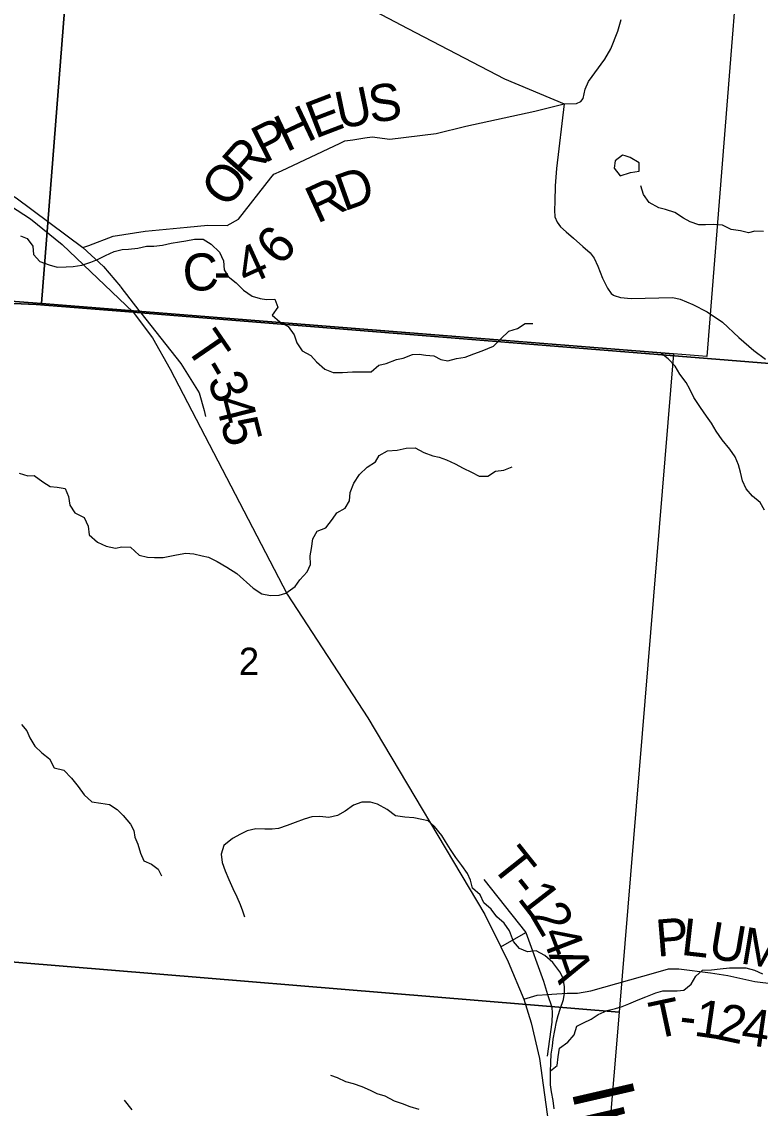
# Model space of a CAD drawing. Extents: x 1715311 to 2083412, y 146837 to 553079.
# Drawn here: x 1973537 to 1979519, y 339371 to 348173 of the extents above; entities that cross this region are included whole.
import ezdxf

# ---------------------------------------------------------------- set-up
doc = ezdxf.new("R2010")
doc.units = 0
for name, color, linetype in [('GM_X_County_Road', 7, 'Continuous'), ('GM_X_County_Road_Text', 7, 'Continuous'), ('GM_X_Minor_Lake', 7, 'Continuous'), ('GM_X_Minor_River', 7, 'Continuous'), ('GM_X_Minor_River_Text', 7, 'Continuous'), ('GM_X_Section', 7, 'Continuous'), ('GM_X_Section_Text', 7, 'Continuous'), ('GM_X_Township', 7, 'Continuous'), ('GM_X_Township_Road', 7, 'Continuous'), ('GM_X_Township_Road_Text', 7, 'Continuous'), ('GM_X_Township_ROW', 7, 'Continuous'), ('GM_X_US_Route', 7, 'Continuous')]:
    doc.layers.add(name, color=color, linetype=linetype)

msp = doc.modelspace()

# ---------------------------------------------------------------- linework, layer by layer
at = {"layer": 'GM_X_County_Road'}
for points in [[(1976315.6, 347231.9), (1976375.3, 347240.8), (1976518, 347221.4), (1976893.4, 347268.9), (1977134.7, 347326.6), (1977693.6, 347448.3), (1977931.9, 347509.1), (1978031.9, 347510.2), (1978065.9, 347526.7), (1978085.5, 347551.4), (1978102, 347625.6), (1978126.8, 347689.6), (1978260.8, 347869.1), (1978310.3, 347953.6), (1978366, 348098), (1978392.8, 348190.8)], [(1974080.1, 346361.4), (1974277.8, 346435.5), (1974537.4, 346476.2), (1974707.9, 346491.5), (1974878.3, 346509.3), (1975043.7, 346524.6), (1975201.5, 346522), (1975293.1, 346572.9), (1975554.3, 346908.1), (1975579.5, 346937.2), (1975640.1, 346965.7), (1976117.7, 347190.6), (1976154.1, 347207.7), (1976218.7, 347217.4), (1976315.6, 347231.9)], [(1972738.2, 347039.8), (1972777.2, 347075.4), (1972816.1, 347111), (1972838.6, 347131.6), (1972902.1, 347091.5), (1973491.6, 346746), (1974033.6, 346343.9), (1974080.1, 346361.4)]]:
    msp.add_lwpolyline(points, dxfattribs=at)
at = {"layer": 'GM_X_Minor_Lake'}
for points in [[(1978424.9, 347085.7), (1978402.6, 347092.6), (1978344.8, 347046.4), (1978336.9, 346986.3), (1978385, 346924.3)], [(1978385, 346924.3), (1978468.8, 346952.6), (1978538.7, 346962.7), (1978538.5, 347028.8), (1978466.6, 347072.7), (1978424.9, 347085.7)]]:
    msp.add_lwpolyline(points, dxfattribs=at)
at = {"layer": 'GM_X_Minor_River'}
for points in [[(1979544.2, 346474.2), (1979476.2, 346476), (1979424.3, 346461.9), (1979358.4, 346479.8), (1979284.5, 346489.6), (1979212.5, 346525.5), (1979138.6, 346531.4), (1979074.7, 346527.2), (1979020.8, 346529.1), (1978950.8, 346553), (1978896.9, 346581), (1978826.9, 346626.9), (1978750.9, 346650.7), (1978697, 346664.6), (1978619, 346708.5), (1978573, 346774.5), (1978550.9, 346842.6)], [(1973526.7, 346437.7), (1973582.6, 346417.8), (1973626.7, 346353.8), (1973632.8, 346287.8), (1973684.8, 346231.8), (1973760.8, 346203.9), (1973824.7, 346186), (1973898.6, 346188.1), (1973954.5, 346190.3), (1974024.4, 346200.4), (1974098.3, 346226.6), (1974150.2, 346246.8), (1974216, 346278.9), (1974285.9, 346311.1), (1974349.7, 346329.3), (1974401.7, 346329.4), (1974477.5, 346339.5), (1974547.4, 346353.7), (1974607.3, 346355.8), (1974677.2, 346362), (1974749.1, 346380.1), (1974815, 346390.3), (1974866.9, 346398.4), (1974936.8, 346410.6), (1975006.7, 346412.7), (1975072.6, 346370.8), (1975138.7, 346306.8), (1975172.8, 346236.8), (1975176.9, 346162.7), (1975208.9, 346108.7), (1975274.9, 346056.8), (1975333, 345998.8), (1975403, 345950.9), (1975468.9, 345931), (1975520.8, 345923.1), (1975586.8, 345925.3), (1975612.8, 345861.2), (1975567, 345797.1), (1975629, 345743.1), (1975695, 345703.2), (1975745.1, 345637.2), (1975765.2, 345571.2), (1975809.2, 345507.2), (1975879.2, 345469.3), (1975925.2, 345417.3), (1975991.2, 345359.4), (1976059.2, 345331.5), (1976135.1, 345331.6), (1976217, 345337.8), (1976288.9, 345336), (1976366.8, 345336.1), (1976428.6, 345390.3), (1976490.5, 345404.5), (1976572.3, 345436.7), (1976628.2, 345446.8), (1976702, 345477), (1976755.9, 345479.1), (1976809.9, 345471.2), (1976875.8, 345465.3), (1976931.8, 345437.4), (1976989.7, 345425.5), (1977059.6, 345443.7), (1977129.5, 345455.8), (1977199.3, 345484), (1977267.2, 345508.2), (1977359, 345544.4), (1977418.8, 345604.6), (1977482.6, 345666.8), (1977552.4, 345689), (1977614.3, 345727.2), (1977678.2, 345729.3)], [(1979271.8, 344711.3), (1979209.8, 344787.3), (1979161.7, 344857.3), (1979123.7, 344921.3), (1979083.6, 344977.3), (1979035.5, 345049.3), (1978981.5, 345129.3), (1978949.4, 345197.3), (1978919.3, 345249.3), (1978867.3, 345317.2), (1978829.2, 345383.3), (1978773.2, 345443.2), (1978707.2, 345493.1)], [(1973516.3, 344517.2), (1973586.2, 344493.4), (1973638.2, 344497.5), (1973708.1, 344445.6), (1973768.1, 344407.6), (1973824.1, 344401.8), (1973888, 344391.9), (1973916.1, 344325.8), (1973928.2, 344255.8), (1973968.3, 344193.8), (1974044.2, 344155.9), (1974074.3, 344085.9), (1974084.4, 344015.8), (1974150.4, 343957.9), (1974222.4, 343924), (1974296.3, 343908.1), (1974348.2, 343918.2), (1974418.1, 343916.4), (1974488.2, 343850.5), (1974556.1, 343836.6), (1974614, 343832.7), (1974683.9, 343832.8), (1974735.8, 343842.9), (1974789.7, 343853.1), (1974865.6, 343869.2), (1974931.5, 343861.4), (1974999.5, 343847.5), (1975051.4, 343835.6), (1975121.4, 343799.7), (1975197.4, 343755.8), (1975279.3, 343703.9), (1975411.4, 343584), (1975481.4, 343538.1), (1975551.3, 343526.2), (1975621.2, 343528.4), (1975677.1, 343544.5), (1975750.9, 343598.7), (1975790.7, 343652.9), (1975850.5, 343717.1), (1975876.4, 343777.2), (1975874.2, 343845.3), (1975884.1, 343905.4), (1975895.9, 343983.5), (1975929.8, 344045.6), (1975999.6, 344073.8), (1976055.4, 344142), (1976089.3, 344194.1), (1976157.1, 344232.3), (1976191, 344292.5), (1976198.8, 344360.6), (1976226.6, 344434.7), (1976272.4, 344504.9), (1976334.2, 344565.1), (1976402.1, 344607.3), (1976431.9, 344659.4), (1976499.8, 344695.6), (1976577.6, 344701.8), (1976651.5, 344717.9), (1976725.4, 344720.1), (1976795.4, 344682.2), (1976867.3, 344656.3), (1976919.3, 344646.4), (1976977.2, 344624.5), (1977049.2, 344592.6), (1977113.2, 344556.7), (1977179.1, 344522.8), (1977243.1, 344490.9), (1977313, 344491), (1977374.8, 344533.2), (1977442.7, 344541.3), (1977510.6, 344567.5)], [(1979554.4, 344215.3), (1979518.3, 344279.3), (1979456.3, 344329.2), (1979406.2, 344389.2), (1979376.2, 344455.2), (1979358.1, 344523.3), (1979344, 344583.3), (1979315.9, 344647.3), (1979271.8, 344711.3)], [(1973536, 342480.9), (1973578.1, 342429), (1973604.2, 342373), (1973644.2, 342305), (1973700.2, 342251), (1973762.3, 342201.1), (1973800.3, 342129.1), (1973878.3, 342109.2), (1973940.3, 342045.3), (1973994.3, 341977.3), (1974042.4, 341911.3), (1974106.4, 341853.4), (1974178.3, 341841.5), (1974248.3, 341831.7), (1974310.2, 341791.8), (1974360.3, 341743.8), (1974418.3, 341671.8), (1974446.4, 341621.8), (1974454.5, 341567.8), (1974476.5, 341509.8), (1974498.6, 341437.7), (1974526.7, 341375.7), (1974588.7, 341347.8), (1974642.7, 341307.9), (1974670.7, 341253.9)], [(1977836.9, 339874.7), (1977842.7, 339930.8), (1977856.6, 340000.9), (1977868.5, 340071), (1977882.3, 340123.1), (1977898.2, 340173.2), (1977926, 340251.3), (1977933.9, 340303.4), (1977933.8, 340353.5), (1977921.7, 340425.5), (1977895.7, 340475.5), (1977839.6, 340551.5), (1977773.6, 340609.4), (1977703.6, 340647.3), (1977633.7, 340637.2), (1977569.8, 340665.1), (1977519.7, 340723), (1977487.6, 340807.1), (1977445.6, 340871.1), (1977385.5, 340923), (1977339.5, 340985), (1977279.5, 341034.9), (1977251.4, 341100.9), (1977187.4, 341154.9), (1977173.3, 341218.9), (1977149.2, 341272.9), (1977103.2, 341338.9), (1977053.1, 341402.9), (1977011.1, 341466.9), (1976971, 341530.9), (1976938.9, 341580.8), (1976880.9, 341652.8), (1976828.9, 341698.8), (1976776.9, 341710.7), (1976713, 341722.5), (1976641.1, 341728.4), (1976565.2, 341740.3), (1976497.2, 341790.2), (1976419.2, 341834.1), (1976363.3, 341850), (1976293.3, 341851.8), (1976225.5, 341827.7), (1976157.7, 341777.5), (1976093.8, 341741.3), (1976024, 341725.1), (1975952.1, 341735), (1975886.1, 341732.9), (1975826.3, 341712.7), (1975752.4, 341686.5), (1975686.6, 341662.4), (1975616.7, 341638.2), (1975564.8, 341632.1), (1975506.9, 341632), (1975433, 341633.8), (1975363.1, 341617.7), (1975309.2, 341591.5), (1975243.4, 341557.4), (1975173.6, 341499.2), (1975153.7, 341429.1), (1975161.8, 341363), (1975185.9, 341295), (1975216, 341225), (1975248.1, 341150.9), (1975280.2, 341084.9), (1975306.3, 341022.9), (1975324.3, 340970.9), (1975342.4, 340920.9)], [(1977821.4, 339672.9), (1977875.1, 339718.6), (1977883, 339786.7), (1977892.8, 339856.8), (1977960.6, 339905), (1978012.4, 339965.2), (1978032.3, 340035.3), (1978088.2, 340063.4), (1978150, 340093.6), (1978205.9, 340129.8), (1978279.7, 340163.9), (1978345.6, 340180.1), (1978401.5, 340194.2), (1978455.4, 340216.3), (1978531.2, 340250.5), (1978591.1, 340274.7), (1978672.9, 340306.9), (1978728.8, 340321), (1978792.7, 340321.2), (1978846.6, 340323.3), (1978900.5, 340327.4), (1978960.3, 340375.6), (1978998.2, 340439.7), (1979052, 340489.9), (1979123.9, 340492), (1979195.8, 340500.2), (1979269.7, 340508.3), (1979401.5, 340508.6), (1979471.4, 340488.7), (1979537.4, 340460.8)], [(1977849.8, 339366.1), (1977841.7, 339434.2), (1977829.6, 339504.3), (1977821.5, 339560.3), (1977821.3, 339666.4), (1977823.1, 339740.5), (1977827, 339808.6), (1977836.9, 339874.7)], [(1976755.3, 339361.9), (1976683.4, 339383.8), (1976621.4, 339407.7), (1976557.5, 339427.6), (1976481.5, 339469.5), (1976415.6, 339487.4), (1976363.6, 339515.3), (1976295.6, 339543.2), (1976223.7, 339569.1), (1976163.7, 339585), (1976095.8, 339616.9), (1976041.8, 339636.8)], [(1974430.6, 339359.3), (1974370.5, 339435.2)]]:
    msp.add_lwpolyline(points, dxfattribs=at)
at = {"layer": 'GM_X_Section'}
for points in [[(1968750.1, 351653.6), (1974119.3, 351259.5), (1973697, 345890.3), (1973160.9, 345929.9), (1968371.3, 346279.5)], [(1974119.3, 351259.5), (1979516.5, 350859.4), (1979086.3, 345460.2), (1978816.2, 345484), (1973697, 345890.3)], [(1973160.9, 345929.9), (1973697, 345890.3), (1978816.2, 345484), (1978376, 340148.7), (1972760.7, 340612.8)], [(1972760.7, 340612.8), (1978376, 340148.7), (1977933.7, 334861.5), (1972308.4, 335313.6)]]:
    msp.add_lwpolyline(points, close=True, dxfattribs=at)
at = {"layer": 'GM_X_Township'}
for points in [[(1985738.3, 360944.3), (1985383.8, 356640.2), (1984847.2, 350030.1), (1984507.3, 345999.8), (1984436.4, 345172.5), (1984423, 345015.2), (1982277.8, 345208.6), (1981975, 345225.2), (1981635.9, 345260.4), (1981067.6, 345285.4), (1974501.5, 345814.1), (1974438.7, 345819.2), (1973653.8, 345882.4), (1973102.2, 345907.8), (1968500.1, 346272.2), (1967594.7, 346346.7), (1967018.4, 346390), (1960705.7, 346899.9)], [(1960705.7, 346899.9), (1967018.4, 346390), (1967594.7, 346346.7), (1968500.1, 346272.2), (1973102.2, 345907.8), (1973653.8, 345882.4), (1974438.7, 345819.2), (1974501.5, 345814.1), (1981067.6, 345285.4), (1981635.9, 345260.4), (1981975, 345225.2), (1982277.8, 345208.6), (1984423, 345015.2), (1984006.9, 340156), (1983804.4, 337791.6)]]:
    msp.add_lwpolyline(points, dxfattribs=at)
at = {"layer": 'GM_X_Township_Road'}
for points in [[(1975971.4, 348485.6), (1976666, 348118.6), (1977446.6, 347711.3), (1977931.9, 347509.1)], [(1977931.9, 347509.1), (1977868.4, 346985.4), (1977859.3, 346843.3), (1977856.3, 346716.3), (1977851.8, 346646.8), (1977856.3, 346593.9), (1977874.5, 346550.1), (1977901.7, 346510.8), (1977948.5, 346469.9), (1978006, 346420.2)], [(1978006, 346420.2), (1978083.1, 346353.6), (1978140.5, 346302.2), (1978175.2, 346256.8), (1978204, 346191.8), (1978241.7, 346095.1), (1978282.6, 346013.5), (1978312.8, 345971.2), (1978330.8, 345958)], [(1974033.6, 346343.9), (1974200.1, 346191), (1974337.7, 346027.6)], [(1974337.7, 346027.6), (1974341.4, 346023.2), (1974486.4, 345833.8)], [(1978330.8, 345958), (1978335.4, 345954.5), (1978386.9, 345937.9), (1978474.5, 345930.3), (1978810.1, 345937.9), (1978870.5, 345924.3), (1978971.8, 345883.5), (1979089.7, 345823), (1979212.1, 345739.9), (1979346.6, 345614.5), (1979466.1, 345508.7), (1979561.3, 345439.1)], [(1974486.4, 345833.8), (1974501.5, 345814.1), (1974827.4, 345405), (1974975, 345165.8), (1975014.4, 345023.2), (1975024.9, 344975.3)], [(1977280.3, 341223.4), (1977621.4, 340794.5), (1977763.2, 340401.3), (1977796.3, 340293.5), (1977830.8, 340188.6), (1977833.7, 340141.2), (1977832.2, 340067.9), (1977794.1, 339793.7)], [(1977831.7, 340295.4), (1977954.4, 340302.1), (1978037.7, 340302.1), (1978147, 340322.3), (1978673, 340471.7), (1978776.5, 340500.5), (1978859.8, 340500.5), (1979115.7, 340468.8), (1979256.5, 340445.8), (1979475, 340397), (1979914.8, 340345.1), (1979923.8, 340344.5), (1979996.1, 340297.7), (1980116, 340220), (1980119.4, 340217.8)], [(1977605.2, 340254.7), (1977712.9, 340287.8), (1977796.3, 340293.5), (1977831.7, 340295.4)]]:
    msp.add_lwpolyline(points, dxfattribs=at)
at = {"layer": 'GM_X_Township_ROW'}
msp.add_lwpolyline([(1977418.7, 340678.2), (1977621.4, 340794.5)], dxfattribs=at)
at = {"layer": 'GM_X_US_Route'}
msp.add_lwpolyline([(1971062, 348365.4), (1971265.3, 348113.7), (1971414.9, 347940.2), (1971765.9, 347623.9), (1971995.7, 347482.6), (1972458.4, 347204.8), (1972738.2, 347039.8), (1973344, 346746), (1973608.6, 346575.5), (1973865.6, 346369.4), (1974438.7, 345819.2), (1974595.9, 345611.1), (1974738.8, 345358.5), (1975687, 343534.6), (1976340.4, 342534.1), (1977289, 340941.7), (1977418.7, 340678.2), (1977478.7, 340556.5), (1977605.2, 340254.7), (1977662.6, 340062.1), (1977731.6, 339774.7), (1978044.3, 337497)], dxfattribs=at)

# ---------------------------------------------------------------- texts
at = {"layer": 'GM_X_County_Road_Text'}
for s, rotation, p in [('U', 11.77215, (1976111.3, 347300.7)), ('S', 7.36135, (1976363.7, 347353.5)), ('E', 20.95782, (1975913.9, 347224)), ('H', 25.30078, (1975680.8, 347113.5)), ('P', 26.73079, (1975501.8, 347023.4)), ('R', 48.71714, (1975363.2, 346856.7)), ('O', 52.25217, (1975204.7, 346651.7)), ('D', 19.66534, (1976146.8, 346635.4)), ('R', 24.84901, (1975929.8, 346534.6)), ('6', 47.61757, (1975629.5, 346183.9)), ('4', 24.48546, (1975355.1, 346030)), ('C', 4.03501, (1974851.7, 345985.5)), ('-', 359.00861, (1975090.5, 346002.7))]:
    msp.add_text(s, height=300, rotation=rotation, dxfattribs=at).set_placement(p)
at = {"layer": 'GM_X_Minor_River_Text'}
msp.add_text('Indian', height=499.92, rotation=283.00144, dxfattribs=at).set_placement((1977986.2, 339520.5))
at = {"layer": 'GM_X_Section_Text'}
msp.add_text('2', height=221, rotation=0.00001, dxfattribs=at).set_placement((1975296, 342881.1))
at = {"layer": 'GM_X_Township_Road_Text'}
for s, rotation, p in [('T', 304.4797, (1974854.9, 345542)), ('-', 300.63399, (1974978.9, 345361.9)), ('3', 291.97907, (1975035.8, 345267.5)), ('4', 284.27515, (1975101.1, 345107.7)), ('5', 284.27515, (1975146.3, 344930)), ('T', 308.49696, (1977331.1, 341338.9)), ('-', 308.49689, (1977470.5, 341163.6)), ('1', 307.68456, (1977545.8, 341068.9)), ('2', 300.36495, (1977652.2, 340932.3)), ('P', 4.69025, (1978684.4, 340598)), ('L', 353.52351, (1978870.7, 340614.8)), ('U', 350.49276, (1979089.5, 340590)), ('M', 350.53166, (1979350.1, 340546.4)), ('4', 290.96725, (1977739.3, 340785.8)), ('A', 289.13244, (1977804, 340617)), ('T', 12.01005, (1978660.4, 339929.3)), ('1', 351.7227, (1978974.3, 339960.5)), ('2', 347.86744, (1979151.9, 339934.9)), ('4', 351.81842, (1979354.8, 339892.1)), ('-', 353.23225, (1978854, 339974.8))]:
    msp.add_text(s, height=300, rotation=rotation, dxfattribs=at).set_placement(p)

doc.saveas('drawing.dxf')
